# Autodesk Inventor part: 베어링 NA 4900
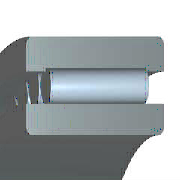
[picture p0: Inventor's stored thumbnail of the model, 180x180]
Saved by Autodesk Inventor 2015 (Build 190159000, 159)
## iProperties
Created: 2009-02
Part Number: 베어링 NA 4900
Material: 스테인리스강
Description: 니들 롤러 베어링 - 경계 치수 및 공차
Document SubType Name: Modeling
Standard: KS B 2029
Designer: SeoGD™
Standards Organization: KS
Language: ko-KR
Size Designation: NA 4900 - 10 x 22 x 13
Categories: <MemberInstance><Categories><Category DisplayName="샤프트 부품" InternalName="7f7aeb1f-a693-4053-b835-cee3144e0d98" Mnemonic="SHFT"><Category DisplayName="베어링" Inter
Density: 1 g/cm^3
Appearance: 반광택
IsCustomPart: 0
Author: SeoGD™
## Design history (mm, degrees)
sketch "스케치"
  geometry: L1 (1.857, 9)-(11.143, 9); L2 (11.143, 9)-(11.143, 7); L3 (13, 7)-(0, 7); L4 (1.857, 7)-(1.857, 9); L5 (1.857, 8)-(11.143, 8); L6 (6.5, 8)-(6.5, 7); L7 (0, 5)-(13, 5); L8 (0, 11)-(13, 11); L9 (13, 5)-(13, 7); L10 (13, 8.8)-(13, 11); L11 (1.857, 8.8)-(0, 8.8); L12 (11.143, 8.8)-(13, 8.8); L13 (-6, 0)-(36, 0) reference; L14 (0, -1.9)-(0, 14.9) reference
  constraints: 24 end point, 8 point on line, 3 midpoint, 3 parallel, 3 perpendicular, 2 symmetric about line, 1 horizontal, 1 other
  dimensions: "d6" = 10 diameter of L7 L13 (= WD); "d7" = 14 diameter of L3 L13 (= KID1); "d8" = 22 diameter of L8 L13 (= BD); "d9" = 16 diameter of L6.start L13 (= 0.5 x WD + 0.5 x BD); "d10" = 17.6 diameter of L12 L13 (= 0.9 x BD + 0.9 x WD - 0.8 x KID1); "d11" = 18 diameter of L1 L13 (= BD + WD - KID1); "d12" = 1.85714 distance between parallel lines of L14 L4 (= 0.142857 x KB); "d13" = 13 distance between parallel lines of L14 L9 (= KB); "d14" = 11.14286 distance between parallel lines of L14 L2 (= 0.857143 x KB)
revolve "본체" stored, may be unused: angle "d17" = 90 deg
revolve "롤러" stored, may be unused: angle "d18" = 90 deg
pattern_circular "IDS_ARRAYROLLER[SIMPL:T]" dims angle "d2" = 360 deg
body "Solid1"
fillet "모깎기1" dims "d0" = 0.3 (= KRS)
other parameters: "WD" = 10 [user parameter; used in 6 equation terms], "BD" = 22 [user parameter; used in 6 equation terms], "KB" = 13 [user parameter; used in 3 equation terms], "KID1" = 14 [user parameter; used in 4 equation terms], "KRS" = 0.3 [user parameter; used in 1 equation term], "d3" = 0, "d4" = 0, "d5" = 0, "d15" = 0, "d16" = 0, "BC0" = 9150000 [user parameter], "WR" = 5 (= 0.5 x WD) [user parameter], "BBA" = 0 [user parameter], "BC" = 8150000 [user parameter], "BR" = 11 (= 0.5 x BD) [user parameter]
